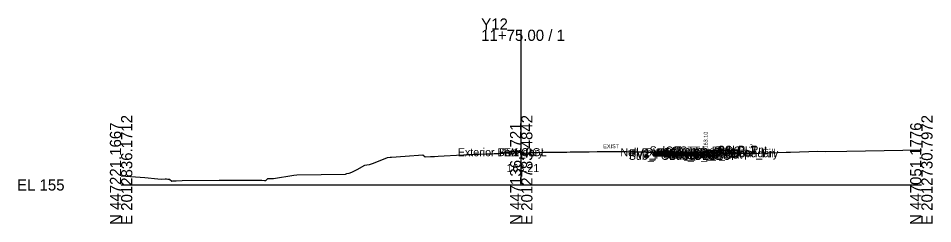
# Model space of a CAD drawing. Extents: x -26 to 1203, y -10 to 9542.
# Drawn here: x -25.7 to 202.8, y 3490.3 to 3541.6 of the extents above; entities that cross this region are included whole.
import ezdxf

# ---------------------------------------------------------------- set-up
doc = ezdxf.new("R2010")
doc.units = 0
for name, color, linetype in [('Default', 7, 'Continuous'), ('Exist Cross Section Cell', 7, 'Continuous'), ('Exist XS Center Line Elevation Label', 7, 'Continuous'), ('Exist XS Ground Line', 7, 'Continuous'), ('Prop CMT Conc Surface', 7, 'Continuous'), ('Prop CMT Concrete Structures', 7, 'Continuous'), ('Prop CMT Pvmt Course 1', 7, 'Continuous'), ('Prop CMT Pvmt Course 1 CG', 7, 'Continuous'), ('Prop CMT Pvmt Course 2', 7, 'Continuous'), ('Prop CMT Pvmt Course 3', 7, 'Continuous'), ('Prop CMT Pvmt Surface', 7, 'Continuous'), ('Prop CMT Slope Grass', 7, 'Continuous'), ('Prop CMT Subgrade Earthwork', 7, 'Continuous'), ('Prop XS Earthwork Shape', 7, 'Continuous'), ('Prop XS Hydro Elevations', 7, 'Continuous'), ('Prop XS SE Text', 7, 'Continuous'), ('Prop XS Side Slope Text', 7, 'Continuous'), ('Scratch_Level_0', 7, 'Continuous')]:
    doc.layers.add(name, color=color, linetype=linetype)

msp = doc.modelspace()

# ---------------------------------------------------------------- linework, layer by layer
at = {"layer": 'Exist Cross Section Cell'}
for p, q in [((100, 3500), (100, 3538.8)), ((0, 3500), (100, 3500)), ((100, 3500), (200, 3500))]:
    msp.add_line(p, q, dxfattribs=at)
at = {"layer": 'Exist XS Ground Line'}
msp.add_lwpolyline([(0, 3502.29), (5.97, 3501.84), (9.17, 3501.51), (9.98, 3501.47), (11, 3501.5), (11.32, 3501.49), (11.69, 3501.48), (12.12, 3501.47), (12.67, 3500.96), (12.97, 3500.99), (13.75, 3501.06), (15.23, 3501.07), (24.55, 3501.19), (33.04, 3501.17), (33.96, 3501.16), (35.14, 3501.16), (35.85, 3501.1), (36.17, 3501.07), (36.69, 3501.57), (38.11, 3501.6), (43.16, 3502.44), (43.95, 3502.52), (56.07, 3502.73), (56.45, 3502.82), (56.98, 3502.94), (57.66, 3503.2), (58.98, 3503.85), (60.95, 3504.94), (61.39, 3505.01), (62.06, 3505.14), (63.04, 3505.44), (66.57, 3506.87), (67.22, 3506.9), (67.56, 3506.93), (71.03, 3507.19), (75.44, 3507.52), (76.03, 3507.05), (77.35, 3507.09), (78, 3507.11), (78.31, 3507.13), (79.26, 3507.18), (80.74, 3507.26), (83.81, 3507.43), (85.54, 3507.52), (86.61, 3507.58), (87.79, 3507.64), (88.23, 3507.67), (89.07, 3507.7), (89.53, 3507.71), (91.15, 3507.76), (92.45, 3507.8), (92.76, 3507.81), (93.26, 3507.83), (94.59, 3507.87), (95.41, 3507.9), (97.88, 3508), (98.26, 3508), (98.94, 3507.91), (99.54, 3508.21), (100, 3508.21), (100.33, 3508.21), (100.93, 3507.91), (101.95, 3508.1), (102.84, 3508.11), (104.26, 3508.14), (105.53, 3508.17), (107.22, 3508.21), (107.55, 3508.21), (110.15, 3508.21), (111.41, 3508.22), (112.2, 3508.23), (112.73, 3508.24), (113.1, 3508.24), (114.42, 3508.27), (116.02, 3508.3), (117.01, 3508.31), (118.94, 3508.33), (121.88, 3508.37), (122.8, 3508.37), (123.3, 3508.37), (124.81, 3508.35), (126.5, 3508.32), (127.75, 3508.3), (129.09, 3508.27), (130.7, 3508.23), (131.18, 3508.22), (132.73, 3508.18), (133.07, 3508.17), (133.66, 3508.2), (134.82, 3508.22), (135.48, 3508.56), (138.2, 3508.2), (138.64, 3508.15), (142.58, 3507.24), (143.36, 3507.34), (145.56, 3507.64), (146.78, 3507.66), (154.08, 3507.84), (159.6, 3507.95), (166.21, 3508.15), (167.26, 3508.19), (174.13, 3508.41), (176.05, 3508.35), (181.38, 3508.46), (200, 3508.73)], dxfattribs=at)
at = {"layer": 'Prop CMT Conc Surface'}
msp.add_lwpolyline([(144.11, 3508.18), (146.11, 3508.1), (146.11, 3508.6), (146.61, 3508.6)], dxfattribs=at)
at = {"layer": 'Prop CMT Concrete Structures'}
for points in [[(144.11, 3508.18), (146.11, 3508.1), (146.11, 3508.6), (146.61, 3508.6)], [(146.61, 3508.6), (146.61, 3507.6), (144.11, 3507.6)], [(144.11, 3507.6), (144.11, 3508.18)]]:
    msp.add_lwpolyline(points, dxfattribs=at)
at = {"layer": 'Prop CMT Pvmt Course 1'}
for points in [[(100, 3508.18), (100, 3508.18)], [(133.07, 3508.18), (133.07, 3508.18)], [(133.07, 3508.18), (144.11, 3508.18)], [(133.07, 3507.93), (133.07, 3508.18)], [(144.11, 3508.18), (144.11, 3507.93)], [(144.11, 3507.93), (133.07, 3507.93)]]:
    msp.add_lwpolyline(points, dxfattribs=at)
at = {"layer": 'Prop CMT Pvmt Course 1 CG'}
for points in [[(144.11, 3507.6), (147.11, 3507.6), (147.45, 3507.27)], [(144.11, 3507.27), (144.11, 3507.6)], [(147.45, 3507.27), (144.11, 3507.27)]]:
    msp.add_lwpolyline(points, dxfattribs=at)
at = {"layer": 'Prop CMT Pvmt Course 2'}
for points in [[(133.07, 3507.6), (133.07, 3507.93)], [(133.07, 3507.93), (144.11, 3507.93)], [(144.11, 3507.6), (133.07, 3507.6)], [(144.11, 3507.93), (144.11, 3507.6)]]:
    msp.add_lwpolyline(points, dxfattribs=at)
at = {"layer": 'Prop CMT Pvmt Course 3'}
for points in [[(133.07, 3507.6), (144.11, 3507.6)], [(133.07, 3507.27), (133.07, 3507.6)], [(144.11, 3507.27), (133.07, 3507.27)], [(144.11, 3507.6), (144.11, 3507.27)]]:
    msp.add_lwpolyline(points, dxfattribs=at)
at = {"layer": 'Prop CMT Pvmt Surface'}
msp.add_lwpolyline([(133.07, 3508.18), (144.11, 3508.18)], dxfattribs=at)
at = {"layer": 'Prop CMT Slope Grass'}
msp.add_lwpolyline([(146.61, 3508.6), (156.11, 3508.79), (158.69, 3507.93)], dxfattribs=at)
at = {"layer": 'Prop CMT Subgrade Earthwork'}
for points in [[(133.07, 3507.27), (133.07, 3508.18)], [(144.11, 3507.27), (147.45, 3507.27), (148.83, 3508.65)], [(133.07, 3507.27), (144.11, 3507.27)], [(144.11, 3507.27), (133.07, 3507.27)]]:
    msp.add_lwpolyline(points, dxfattribs=at)
at = {"layer": 'Prop XS Earthwork Shape'}
for points in [[(133.07, 3508.18), (133.07, 3507.27), (142.46, 3507.27), (138.64, 3508.15), (135.48, 3508.56), (134.82, 3508.22), (133.66, 3508.2), (133.75, 3508.2)], [(147.87, 3507.69), (148.83, 3508.65), (156.11, 3508.79), (158.69, 3507.93), (154.08, 3507.84)], [(142.46, 3507.27), (142.78, 3507.27), (142.58, 3507.24)], [(142.78, 3507.27), (147.45, 3507.27), (147.87, 3507.69), (146.78, 3507.66), (145.56, 3507.64)]]:
    msp.add_lwpolyline(points, close=True, dxfattribs=at)

# ---------------------------------------------------------------- texts
at = {"layer": 'Default'}
msp.add_text('-', height=0.0001, dxfattribs=at).set_placement((0, 3500))
at = {"layer": 'Exist Cross Section Cell'}
for s, p in [('Y12', (90, 3538.8)), ('11+75.00 / 1', (90, 3536)), ('EL 155', (-26, 3498.6))]:
    msp.add_text(s, height=2.8, dxfattribs=at).set_placement(p)
for s, p in [('E 2012836.1712', (2.8, 3490)), ('E 2012783.4842', (102.8, 3490)), ('E 2012730.7972', (202.8, 3490)), ('N 447221.1667', (0, 3490)), ('N 447136.1721', (100, 3490)), ('N 447051.1776', (200, 3490))]:
    msp.add_text(s, height=2.8, rotation=90, dxfattribs=at).set_placement(p)
at = {"layer": 'Exist XS Center Line Elevation Label'}
msp.add_text('163.21', height=2, dxfattribs=at).set_placement((96.32, 3503.21))
at = {"layer": 'Prop XS Hydro Elevations'}
msp.add_text('163.10', height=1, rotation=90, dxfattribs=at).set_placement((146.61, 3509.1))
at = {"layer": 'Prop XS SE Text'}
msp.add_text('EXIST', height=1, rotation=0.0011, dxfattribs=at).set_placement((120.48, 3509.18))
at = {"layer": 'Prop XS Side Slope Text'}
msp.add_text('3:1', height=1, rotation=341.5651, dxfattribs=at).set_placement((156.89, 3509.33))
at = {"layer": 'Scratch_Level_0'}
for s, p in [('Exterior Boundary', (84.14, 3507.18)), ('PV1_PGL', (94.47, 3507.18)), ('EX CL', (95.67, 3507.18)), ('Null Ex EOP', (124.77, 3507.18)), ('Sub_PGL', (126.88, 3506.27)), ('PV2_PGL', (126.98, 3506.93)), ('PV3_PGL', (126.98, 3506.6)), ('PV1', (131.15, 3507.18)), ('Sub_Trench_Out_DLT', (132.09, 3507.65)), ('CG_Top_Face', (136.07, 3507.6)), ('CG1_Shelf_Out', (136.36, 3506.6)), ('CG_Bot_IE', (136.72, 3506.6)), ('Sub_OEOT', (136.89, 3506.27)), ('CG_Top_Gut', (137.04, 3507.1)), ('PV2_OEOT', (136.98, 3506.93)), ('PV3_OEOT', (136.98, 3506.6)), ('CG_Top_BOC', (137.59, 3507.6)), ('CG_Bot_BOC', (137.62, 3506.6)), ('PV1_OEOT', (137.55, 3507.18)), ('Sub_OEOP', (140.25, 3506.27)), ('Exterior Boundary', (142.83, 3506.93)), ('CSLP_Pnt', (148.98, 3507.79)), ('Slope_Fill', (151.9, 3506.93))]:
    msp.add_text(s, height=2, dxfattribs=at).set_placement(p)

doc.saveas('drawing.dxf')
